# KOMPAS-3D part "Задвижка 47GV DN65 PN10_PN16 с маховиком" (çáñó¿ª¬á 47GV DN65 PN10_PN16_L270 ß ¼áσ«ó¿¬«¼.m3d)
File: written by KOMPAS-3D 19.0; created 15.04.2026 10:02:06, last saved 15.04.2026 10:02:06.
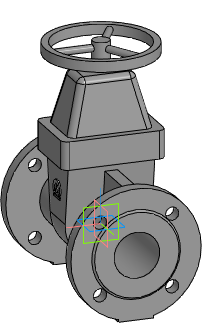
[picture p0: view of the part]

Document properties: Автор: Евгений; Полное имя файла: Z:\3.Личные\kachalov\3d для проектировщиков\2.1 Тип 47GV, 47GV.Z\Задвижка 47GV_DN40-DN600\stp_Задвижка 47GV\Задвижка 47GV DN65 PN10_PN16_L270 с маховиком.m3d

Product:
- Part/product: Задвижка 47GV DN65 PN10_PN16 с маховиком

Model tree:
1. Операция без истории:1  (labels: Задвижка 47GV DN65 PN10_PN16 с маховиком)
